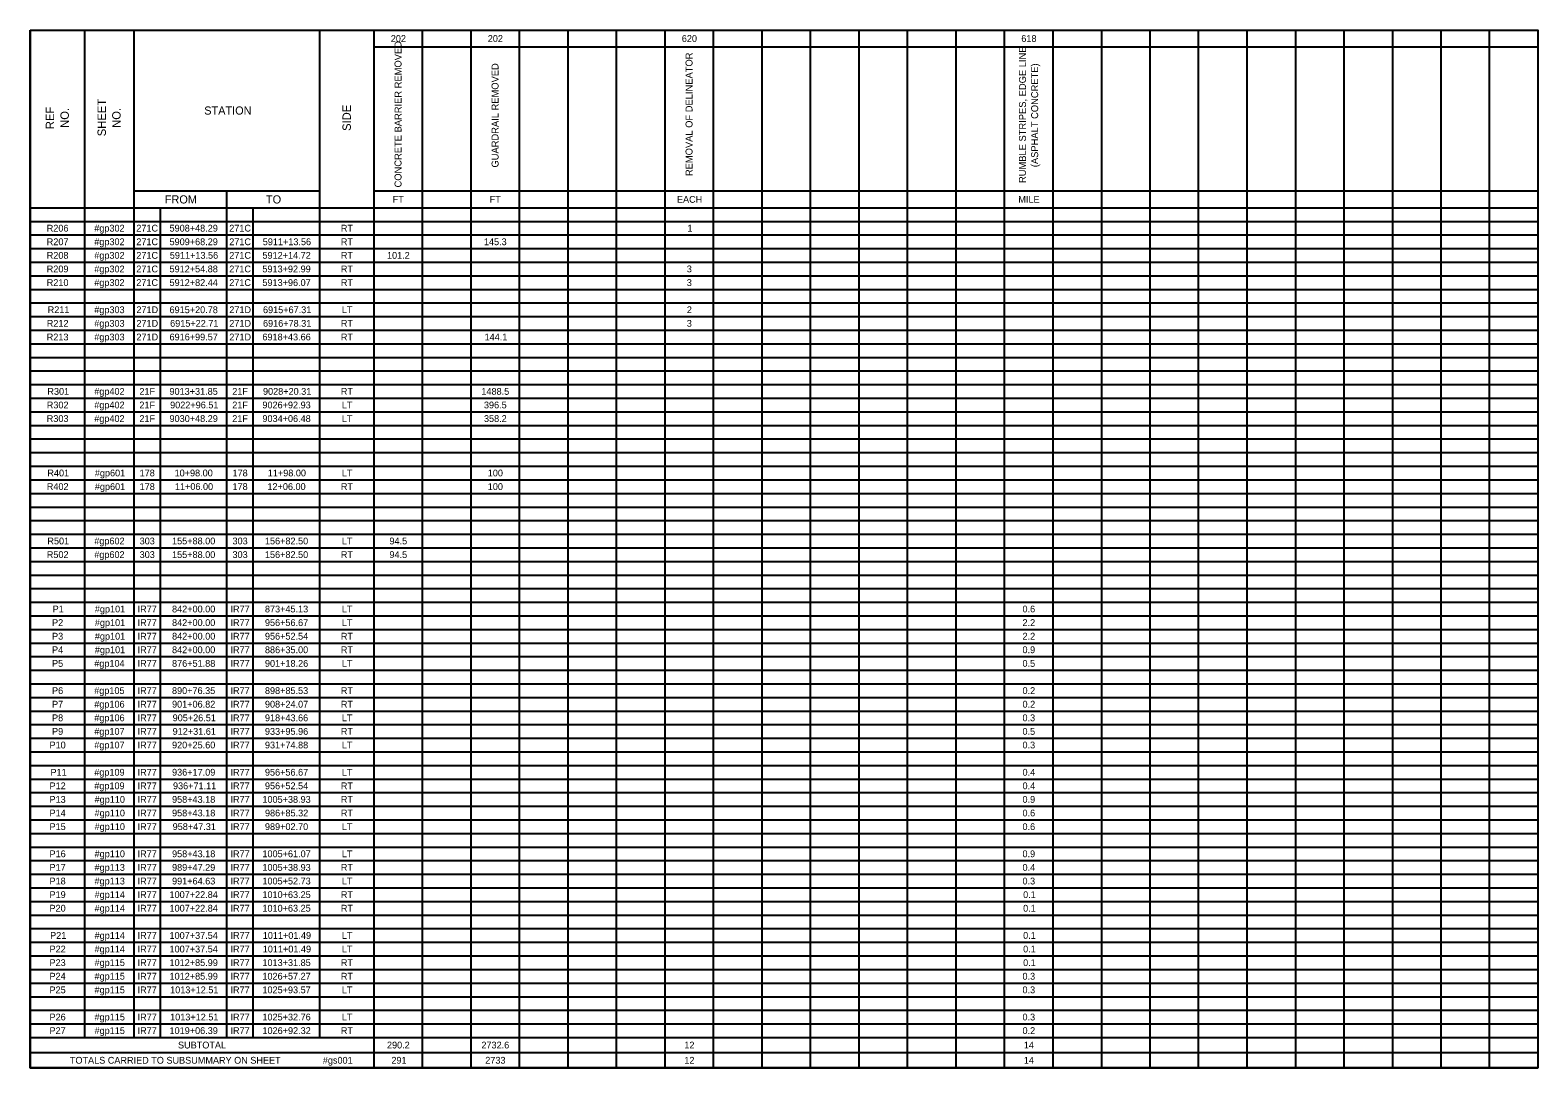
# Model space of a CAD drawing. Extents: x -542 to 295, y -281 to 32.
# Drawn here: x -16.36 to 14.14, y -70.59 to -49.59 of the extents above; entities that cross this region are included whole.
import ezdxf

# ---------------------------------------------------------------- set-up
doc = ezdxf.new("R2010")
doc.units = 0
doc.layers.add('SC_Scratch1', color=7, linetype='Continuous')
doc.layers.add('SH_Text', color=7, linetype='Continuous')

msp = doc.modelspace()

# ---------------------------------------------------------------- linework, layer by layer
at = {"layer": 'SC_Scratch1'}
msp.add_lwpolyline([(-16.359, -49.593), (14.141, -49.593), (14.141, -70.593), (-16.359, -70.593)], close=True, dxfattribs=at)
at = {"layer": 'SH_Text'}
for p, q in [((-16.359, -49.593), (14.141, -49.593)), ((-16.359, -49.593), (-16.359, -70.593)), ((-15.261, -49.593), (-15.261, -69.977)), ((-14.263, -49.593), (-14.263, -69.977)), ((-10.505, -49.593), (-10.505, -69.977)), ((-9.407, -49.593), (-9.407, -70.593)), ((-8.426, -49.593), (-8.426, -70.593)), ((-7.445, -49.593), (-7.445, -70.593)), ((-6.463, -49.593), (-6.463, -70.593)), ((-5.482, -49.593), (-5.482, -70.593)), ((-4.501, -49.593), (-4.501, -70.593)), ((-3.52, -49.593), (-3.52, -70.593)), ((-2.539, -49.593), (-2.539, -70.593)), ((-1.558, -49.593), (-1.558, -70.593)), ((-0.576, -49.593), (-0.576, -70.593)), ((0.405, -49.593), (0.405, -70.593)), ((1.386, -49.593), (1.386, -70.593)), ((2.367, -49.593), (2.367, -70.593)), ((3.348, -49.593), (3.348, -70.593)), ((4.33, -49.593), (4.33, -70.593)), ((5.311, -49.593), (5.311, -70.593)), ((6.292, -49.593), (6.292, -70.593)), ((7.273, -49.593), (7.273, -70.593)), ((8.254, -49.593), (8.254, -70.593)), ((9.236, -49.593), (9.236, -70.593)), ((10.217, -49.593), (10.217, -70.593)), ((11.198, -49.593), (11.198, -70.593)), ((12.179, -49.593), (12.179, -70.593)), ((13.16, -49.593), (13.16, -70.593)), ((14.141, -49.593), (14.141, -70.593)), ((-9.407, -49.933), (14.141, -49.933)), ((-14.263, -52.847), (-10.505, -52.847)), ((-12.384, -52.847), (-12.384, -69.977)), ((-9.407, -52.847), (14.141, -52.847)), ((-16.359, -53.187), (14.141, -53.187)), ((-13.731, -53.187), (-13.731, -69.977)), ((-11.852, -53.187), (-11.852, -69.977)), ((-16.359, -53.462), (14.141, -53.462)), ((-16.359, -53.737), (14.141, -53.737)), ((-16.359, -54.013), (14.141, -54.013)), ((-16.359, -54.288), (14.141, -54.288)), ((-16.359, -54.563), (14.141, -54.563)), ((-16.359, -54.838), (14.141, -54.838)), ((-16.359, -55.114), (14.141, -55.114)), ((-16.359, -55.389), (14.141, -55.389)), ((-16.359, -55.664), (14.141, -55.664)), ((-16.359, -55.94), (14.141, -55.94)), ((-16.359, -56.215), (14.141, -56.215)), ((-16.359, -56.49), (14.141, -56.49)), ((-16.359, -56.765), (14.141, -56.765)), ((-16.359, -57.041), (14.141, -57.041)), ((-16.359, -57.316), (14.141, -57.316)), ((-16.359, -57.591), (14.141, -57.591)), ((-16.359, -57.866), (14.141, -57.866)), ((-16.359, -58.142), (14.141, -58.142)), ((-16.359, -58.417), (14.141, -58.417)), ((-16.359, -58.692), (14.141, -58.692)), ((-16.359, -58.967), (14.141, -58.967)), ((-16.359, -59.243), (14.141, -59.243)), ((-16.359, -59.518), (14.141, -59.518)), ((-16.359, -59.793), (14.141, -59.793)), ((-16.359, -60.068), (14.141, -60.068)), ((-16.359, -60.344), (14.141, -60.344)), ((-16.359, -60.619), (14.141, -60.619)), ((-16.359, -60.894), (14.141, -60.894)), ((-16.359, -61.169), (14.141, -61.169)), ((-16.359, -61.445), (14.141, -61.445)), ((-16.359, -61.72), (14.141, -61.72)), ((-16.359, -61.995), (14.141, -61.995)), ((-16.359, -62.27), (14.141, -62.27)), ((-16.359, -62.546), (14.141, -62.546)), ((-16.359, -62.821), (14.141, -62.821)), ((-16.359, -63.096), (14.141, -63.096)), ((-16.359, -63.371), (14.141, -63.371)), ((-16.359, -63.647), (14.141, -63.647)), ((-16.359, -63.922), (14.141, -63.922)), ((-16.359, -64.197), (14.141, -64.197)), ((-16.359, -64.472), (14.141, -64.472)), ((-16.359, -64.748), (14.141, -64.748)), ((-16.359, -65.023), (14.141, -65.023)), ((-16.359, -65.298), (14.141, -65.298)), ((-16.359, -65.573), (14.141, -65.573)), ((-16.359, -65.849), (14.141, -65.849)), ((-16.359, -66.124), (14.141, -66.124)), ((-16.359, -66.399), (14.141, -66.399)), ((-16.359, -66.674), (14.141, -66.674)), ((-16.359, -66.95), (14.141, -66.95)), ((-16.359, -67.225), (14.141, -67.225)), ((-16.359, -67.5), (14.141, -67.5)), ((-16.359, -67.775), (14.141, -67.775)), ((-16.359, -68.051), (14.141, -68.051)), ((-16.359, -68.326), (14.141, -68.326)), ((-16.359, -68.601), (14.141, -68.601)), ((-16.359, -68.876), (14.141, -68.876)), ((-16.359, -69.152), (14.141, -69.152)), ((-16.359, -69.427), (14.141, -69.427)), ((-16.359, -69.702), (14.141, -69.702)), ((-16.359, -69.977), (14.141, -69.977)), ((-16.359, -70.285), (14.141, -70.285)), ((-16.359, -70.593), (14.141, -70.593))]:
    msp.add_line(p, q, dxfattribs=at)

# ---------------------------------------------------------------- texts
for s, height, p in [('202', 0.1376, (-9.063, -49.831)), ('202', 0.1376, (-7.101, -49.831)), ('620', 0.1376, (-3.176, -49.831)), ('618', 0.1376, (3.692, -49.831)), ('STATION', 0.1652, (-12.837, -51.302)), ('FROM', 0.1652, (-13.635, -53.1)), ('TO', 0.1652, (-11.588, -53.1)), ('FT', 0.1376, (-9.025, -53.086)), ('FT', 0.1376, (-7.062, -53.086)), ('EACH', 0.1376, (-3.274, -53.086)), ('MILE', 0.1376, (3.632, -53.086)), ('R206', 0.1376, (-16.023, -53.669)), ('#gp302', 0.1376, (-15.062, -53.669)), ('271C', 0.1376, (-14.211, -53.669)), ('5908+48.29', 0.1376, (-13.539, -53.669)), ('271C', 0.1376, (-12.331, -53.669)), ('RT', 0.1376, (-10.073, -53.669)), ('1', 0.138, (-3.062, -53.669)), ('R207', 0.1376, (-16.023, -53.944)), ('#gp302', 0.1376, (-15.062, -53.944)), ('271C', 0.1376, (-14.211, -53.944)), ('5909+68.29', 0.1376, (-13.539, -53.944)), ('271C', 0.1376, (-12.331, -53.944)), ('5911+13.56', 0.1376, (-11.653, -53.944)), ('RT', 0.1376, (-10.073, -53.944)), ('145.3', 0.1376, (-7.179, -53.944)), ('R208', 0.1376, (-16.023, -54.219)), ('#gp302', 0.1376, (-15.062, -54.219)), ('271C', 0.1376, (-14.211, -54.219)), ('5911+13.56', 0.1376, (-13.533, -54.219)), ('271C', 0.1376, (-12.331, -54.219)), ('5912+14.72', 0.1376, (-11.659, -54.219)), ('RT', 0.1376, (-10.073, -54.219)), ('101.2', 0.1376, (-9.14, -54.219)), ('R209', 0.1376, (-16.023, -54.494)), ('#gp302', 0.1376, (-15.062, -54.494)), ('271C', 0.1376, (-14.211, -54.494)), ('5912+54.88', 0.1376, (-13.539, -54.494)), ('271C', 0.1376, (-12.331, -54.494)), ('5913+92.99', 0.1376, (-11.66, -54.494)), ('RT', 0.1376, (-10.073, -54.494)), ('3', 0.138, (-3.075, -54.494)), ('R210', 0.1376, (-16.023, -54.77)), ('#gp302', 0.1376, (-15.062, -54.77)), ('271C', 0.1376, (-14.211, -54.77)), ('5912+82.44', 0.1376, (-13.539, -54.77)), ('271C', 0.1376, (-12.331, -54.77)), ('5913+96.07', 0.1376, (-11.66, -54.77)), ('RT', 0.1376, (-10.073, -54.77)), ('3', 0.138, (-3.075, -54.77)), ('R211', 0.1376, (-16.004, -55.32)), ('#gp303', 0.1376, (-15.062, -55.32)), ('271D', 0.1376, (-14.209, -55.32)), ('6915+20.78', 0.1376, (-13.539, -55.32)), ('271D', 0.1376, (-12.33, -55.32)), ('6915+67.31', 0.1376, (-11.648, -55.32)), ('LT', 0.1376, (-10.053, -55.32)), ('2', 0.138, (-3.074, -55.32)), ('R212', 0.1376, (-16.022, -55.595)), ('#gp303', 0.1376, (-15.062, -55.595)), ('271D', 0.1376, (-14.209, -55.595)), ('6915+22.71', 0.1376, (-13.527, -55.595)), ('271D', 0.1376, (-12.33, -55.595)), ('6916+78.31', 0.1376, (-11.648, -55.595)), ('RT', 0.1376, (-10.073, -55.595)), ('3', 0.138, (-3.075, -55.595)), ('R213', 0.1376, (-16.023, -55.871)), ('#gp303', 0.1376, (-15.062, -55.871)), ('271D', 0.1376, (-14.209, -55.871)), ('6916+99.57', 0.1376, (-13.539, -55.871)), ('271D', 0.1376, (-12.33, -55.871)), ('6918+43.66', 0.1376, (-11.66, -55.871)), ('RT', 0.1376, (-10.073, -55.871)), ('144.1', 0.1376, (-7.166, -55.871)), ('R301', 0.1376, (-16.01, -56.972)), ('#gp402', 0.1376, (-15.062, -56.972)), ('21F', 0.1376, (-14.149, -56.972)), ('9013+31.85', 0.1376, (-13.54, -56.972)), ('21F', 0.1376, (-12.27, -56.972)), ('9028+20.31', 0.1376, (-11.648, -56.972)), ('RT', 0.1376, (-10.073, -56.972)), ('1488.5', 0.1376, (-7.23, -56.972)), ('R302', 0.1376, (-16.022, -57.247)), ('#gp402', 0.1376, (-15.062, -57.247)), ('21F', 0.1376, (-14.149, -57.247)), ('9022+96.51', 0.1376, (-13.527, -57.247)), ('21F', 0.1376, (-12.27, -57.247)), ('9026+92.93', 0.1376, (-11.66, -57.247)), ('LT', 0.1376, (-10.053, -57.247)), ('396.5', 0.1376, (-7.179, -57.247)), ('R303', 0.1376, (-16.023, -57.522)), ('#gp402', 0.1376, (-15.062, -57.522)), ('21F', 0.1376, (-14.149, -57.522)), ('9030+48.29', 0.1376, (-13.539, -57.522)), ('21F', 0.1376, (-12.27, -57.522)), ('9034+06.48', 0.1376, (-11.66, -57.522)), ('LT', 0.1376, (-10.053, -57.522)), ('358.2', 0.1376, (-7.178, -57.522)), ('R401', 0.1376, (-16.01, -58.623)), ('#gp601', 0.1376, (-15.05, -58.623)), ('178', 0.1376, (-14.144, -58.623)), ('10+98.00', 0.1376, (-13.437, -58.623)), ('178', 0.1376, (-12.265, -58.623)), ('11+98.00', 0.1376, (-11.551, -58.623)), ('LT', 0.1376, (-10.053, -58.623)), ('100', 0.1376, (-7.101, -58.623)), ('R402', 0.1376, (-16.022, -58.898)), ('#gp601', 0.1376, (-15.05, -58.898)), ('178', 0.1376, (-14.144, -58.898)), ('11+06.00', 0.1376, (-13.43, -58.898)), ('178', 0.1376, (-12.265, -58.898)), ('12+06.00', 0.1376, (-11.558, -58.898)), ('RT', 0.1376, (-10.073, -58.898)), ('100', 0.1376, (-7.101, -58.898)), ('R501', 0.1376, (-16.01, -59.999)), ('#gp602', 0.1376, (-15.062, -59.999)), ('303', 0.1376, (-14.144, -59.999)), ('155+88.00', 0.1376, (-13.488, -59.999)), ('303', 0.1376, (-12.265, -59.999)), ('156+82.50', 0.1376, (-11.609, -59.999)), ('LT', 0.1376, (-10.053, -59.999)), ('94.5', 0.1376, (-9.09, -59.999)), ('R502', 0.1376, (-16.022, -60.275)), ('#gp602', 0.1376, (-15.062, -60.275)), ('303', 0.1376, (-14.144, -60.275)), ('155+88.00', 0.1376, (-13.488, -60.275)), ('303', 0.1376, (-12.265, -60.275)), ('156+82.50', 0.1376, (-11.609, -60.275)), ('RT', 0.1376, (-10.073, -60.275)), ('94.5', 0.1376, (-9.09, -60.275)), ('P1', 0.1376, (-15.904, -61.376)), ('#gp101', 0.1376, (-15.05, -61.376)), ('IR77', 0.1376, (-14.185, -61.376)), ('842+00.00', 0.1376, (-13.488, -61.376)), ('IR77', 0.1376, (-12.306, -61.376)), ('873+45.13', 0.1376, (-11.609, -61.376)), ('LT', 0.1376, (-10.053, -61.376)), ('0.6', 0.1376, (3.716, -61.376)), ('P2', 0.1376, (-15.915, -61.651)), ('#gp101', 0.1376, (-15.05, -61.651)), ('IR77', 0.1376, (-14.185, -61.651)), ('842+00.00', 0.1376, (-13.488, -61.651)), ('IR77', 0.1376, (-12.306, -61.651)), ('956+56.67', 0.1376, (-11.609, -61.651)), ('LT', 0.1376, (-10.053, -61.651)), ('2.2', 0.1376, (3.717, -61.651)), ('P3', 0.1376, (-15.916, -61.926)), ('#gp101', 0.1376, (-15.05, -61.926)), ('IR77', 0.1376, (-14.185, -61.926)), ('842+00.00', 0.1376, (-13.488, -61.926)), ('IR77', 0.1376, (-12.306, -61.926)), ('956+52.54', 0.1376, (-11.609, -61.926)), ('RT', 0.1376, (-10.073, -61.926)), ('2.2', 0.1376, (3.717, -61.926)), ('P4', 0.1376, (-15.916, -62.201)), ('#gp101', 0.1376, (-15.05, -62.201)), ('IR77', 0.1376, (-14.185, -62.201)), ('842+00.00', 0.1376, (-13.488, -62.201)), ('IR77', 0.1376, (-12.306, -62.201)), ('886+35.00', 0.1376, (-11.609, -62.201)), ('RT', 0.1376, (-10.073, -62.201)), ('0.9', 0.1376, (3.716, -62.201)), ('P5', 0.1376, (-15.916, -62.477)), ('#gp104', 0.1376, (-15.062, -62.477)), ('IR77', 0.1376, (-14.185, -62.477)), ('876+51.88', 0.1376, (-13.488, -62.477)), ('IR77', 0.1376, (-12.306, -62.477)), ('901+18.26', 0.1376, (-11.609, -62.477)), ('LT', 0.1376, (-10.053, -62.477)), ('0.5', 0.1376, (3.716, -62.477)), ('P6', 0.1376, (-15.916, -63.027)), ('#gp105', 0.1376, (-15.063, -63.027)), ('IR77', 0.1376, (-14.185, -63.027)), ('890+76.35', 0.1376, (-13.489, -63.027)), ('IR77', 0.1376, (-12.306, -63.027)), ('898+85.53', 0.1376, (-11.609, -63.027)), ('RT', 0.1376, (-10.073, -63.027)), ('0.2', 0.1376, (3.717, -63.027)), ('P7', 0.1376, (-15.916, -63.302)), ('P8', 0.1376, (-15.916, -63.578)), ('#gp106', 0.1376, (-15.062, -63.302)), ('#gp106', 0.1376, (-15.062, -63.578)), ('IR77', 0.1376, (-14.185, -63.302)), ('901+06.82', 0.1376, (-13.488, -63.302)), ('905+26.51', 0.1376, (-13.476, -63.578)), ('IR77', 0.1376, (-12.306, -63.302)), ('908+24.07', 0.1376, (-11.609, -63.302)), ('918+43.66', 0.1376, (-11.609, -63.578)), ('RT', 0.1376, (-10.073, -63.302)), ('0.2', 0.1376, (3.717, -63.302)), ('0.3', 0.1376, (3.716, -63.578)), ('P9', 0.1376, (-15.916, -63.853)), ('#gp107', 0.1376, (-15.062, -63.853)), ('IR77', 0.1376, (-14.185, -63.578)), ('IR77', 0.1376, (-14.185, -63.853)), ('912+31.61', 0.1376, (-13.476, -63.853)), ('IR77', 0.1376, (-12.306, -63.578)), ('IR77', 0.1376, (-12.306, -63.853)), ('933+95.96', 0.1376, (-11.609, -63.853)), ('RT', 0.1376, (-10.073, -63.853)), ('LT', 0.1376, (-10.053, -63.578)), ('0.5', 0.1376, (3.716, -63.853)), ('P10', 0.1376, (-15.967, -64.128)), ('#gp107', 0.1376, (-15.062, -64.128)), ('IR77', 0.1376, (-14.185, -64.128)), ('920+25.60', 0.1376, (-13.488, -64.128)), ('IR77', 0.1376, (-12.306, -64.128)), ('931+74.88', 0.1376, (-11.609, -64.128)), ('LT', 0.1376, (-10.053, -64.128)), ('0.3', 0.1376, (3.716, -64.128)), ('P11', 0.1376, (-15.948, -64.679)), ('#gp109', 0.1376, (-15.062, -64.679)), ('IR77', 0.1376, (-14.185, -64.679)), ('936+17.09', 0.1376, (-13.488, -64.679)), ('IR77', 0.1376, (-12.306, -64.679)), ('956+56.67', 0.1376, (-11.609, -64.679)), ('LT', 0.1376, (-10.053, -64.679)), ('0.4', 0.1376, (3.717, -64.679)), ('P12', 0.1376, (-15.966, -64.954)), ('#gp109', 0.1376, (-15.062, -64.954)), ('IR77', 0.1376, (-14.185, -64.954)), ('936+71.11', 0.1376, (-13.469, -64.954)), ('IR77', 0.1376, (-12.306, -64.954)), ('956+52.54', 0.1376, (-11.609, -64.954)), ('RT', 0.1376, (-10.073, -64.954)), ('0.4', 0.1376, (3.717, -64.954)), ('P13', 0.1376, (-15.967, -65.229)), ('#gp110', 0.1376, (-15.055, -65.229)), ('IR77', 0.1376, (-14.185, -65.229)), ('958+43.18', 0.1376, (-13.488, -65.229)), ('IR77', 0.1376, (-12.306, -65.229)), ('1005+38.93', 0.1376, (-11.66, -65.229)), ('RT', 0.1376, (-10.073, -65.229)), ('0.9', 0.1376, (3.716, -65.229)), ('P14', 0.1376, (-15.967, -65.504)), ('#gp110', 0.1376, (-15.055, -65.504)), ('IR77', 0.1376, (-14.185, -65.504)), ('958+43.18', 0.1376, (-13.488, -65.504)), ('IR77', 0.1376, (-12.306, -65.504)), ('986+85.32', 0.1376, (-11.608, -65.504)), ('RT', 0.1376, (-10.073, -65.504)), ('0.6', 0.1376, (3.716, -65.504)), ('P15', 0.1376, (-15.967, -65.78)), ('#gp110', 0.1376, (-15.055, -65.78)), ('IR77', 0.1376, (-14.185, -65.78)), ('958+47.31', 0.1376, (-13.476, -65.78)), ('IR77', 0.1376, (-12.306, -65.78)), ('989+02.70', 0.1376, (-11.609, -65.78)), ('LT', 0.1376, (-10.053, -65.78)), ('0.6', 0.1376, (3.716, -65.78)), ('P16', 0.1376, (-15.967, -66.33)), ('P17', 0.1376, (-15.967, -66.605)), ('#gp110', 0.1376, (-15.055, -66.33)), ('#gp113', 0.1376, (-15.056, -66.605)), ('IR77', 0.1376, (-14.185, -66.33)), ('IR77', 0.1376, (-14.185, -66.605)), ('958+43.18', 0.1376, (-13.488, -66.33)), ('989+47.29', 0.1376, (-13.488, -66.605)), ('IR77', 0.1376, (-12.306, -66.33)), ('IR77', 0.1376, (-12.306, -66.605)), ('1005+61.07', 0.1376, (-11.66, -66.33)), ('1005+38.93', 0.1376, (-11.66, -66.605)), ('RT', 0.1376, (-10.073, -66.605)), ('LT', 0.1376, (-10.053, -66.33)), ('0.9', 0.1376, (3.716, -66.33)), ('0.4', 0.1376, (3.717, -66.605)), ('P18', 0.1376, (-15.967, -66.881)), ('#gp113', 0.1376, (-15.056, -66.881)), ('IR77', 0.1376, (-14.185, -66.881)), ('991+64.63', 0.1376, (-13.488, -66.881)), ('IR77', 0.1376, (-12.306, -66.881)), ('1005+52.73', 0.1376, (-11.66, -66.881)), ('LT', 0.1376, (-10.053, -66.881)), ('0.3', 0.1376, (3.716, -66.881)), ('P19', 0.1376, (-15.967, -67.156)), ('#gp114', 0.1376, (-15.055, -67.156)), ('IR77', 0.1376, (-14.185, -67.156)), ('1007+22.84', 0.1376, (-13.539, -67.156)), ('IR77', 0.1376, (-12.306, -67.156)), ('1010+63.25', 0.1376, (-11.66, -67.156)), ('RT', 0.1376, (-10.073, -67.156)), ('0.1', 0.1376, (3.729, -67.156)), ('P20', 0.1376, (-15.967, -67.431)), ('#gp114', 0.1376, (-15.055, -67.431)), ('IR77', 0.1376, (-14.185, -67.431)), ('1007+22.84', 0.1376, (-13.539, -67.431)), ('IR77', 0.1376, (-12.306, -67.431)), ('1010+63.25', 0.1376, (-11.66, -67.431)), ('RT', 0.1376, (-10.073, -67.431)), ('0.1', 0.1376, (3.729, -67.431)), ('P21', 0.1376, (-15.955, -67.982)), ('#gp114', 0.1376, (-15.055, -67.982)), ('IR77', 0.1376, (-14.185, -67.982)), ('1007+37.54', 0.1376, (-13.539, -67.982)), ('IR77', 0.1376, (-12.306, -67.982)), ('1011+01.49', 0.1376, (-11.653, -67.982)), ('LT', 0.1376, (-10.053, -67.982)), ('0.1', 0.1376, (3.729, -67.982)), ('P22', 0.1376, (-15.966, -68.257)), ('#gp114', 0.1376, (-15.055, -68.257)), ('IR77', 0.1376, (-14.185, -68.257)), ('1007+37.54', 0.1376, (-13.539, -68.257)), ('IR77', 0.1376, (-12.306, -68.257)), ('1011+01.49', 0.1376, (-11.653, -68.257)), ('LT', 0.1376, (-10.053, -68.257)), ('0.1', 0.1376, (3.729, -68.257)), ('P23', 0.1376, (-15.967, -68.532)), ('#gp115', 0.1376, (-15.056, -68.532)), ('IR77', 0.1376, (-14.185, -68.532)), ('1012+85.99', 0.1376, (-13.539, -68.532)), ('IR77', 0.1376, (-12.306, -68.532)), ('1013+31.85', 0.1376, (-11.66, -68.532)), ('RT', 0.1376, (-10.073, -68.532)), ('0.1', 0.1376, (3.729, -68.532)), ('P24', 0.1376, (-15.967, -68.807)), ('#gp115', 0.1376, (-15.056, -68.807)), ('IR77', 0.1376, (-14.185, -68.807)), ('1012+85.99', 0.1376, (-13.539, -68.807)), ('IR77', 0.1376, (-12.306, -68.807)), ('1026+57.27', 0.1376, (-11.66, -68.807)), ('RT', 0.1376, (-10.073, -68.807)), ('0.3', 0.1376, (3.716, -68.807)), ('P25', 0.1376, (-15.967, -69.083)), ('#gp115', 0.1376, (-15.056, -69.083)), ('IR77', 0.1376, (-14.185, -69.083)), ('1013+12.51', 0.1376, (-13.527, -69.083)), ('IR77', 0.1376, (-12.306, -69.083)), ('1025+93.57', 0.1376, (-11.66, -69.083)), ('LT', 0.1376, (-10.053, -69.083)), ('0.3', 0.1376, (3.716, -69.083)), ('P26', 0.1376, (-15.967, -69.633)), ('#gp115', 0.1376, (-15.056, -69.633)), ('IR77', 0.1376, (-14.185, -69.633)), ('1013+12.51', 0.1376, (-13.527, -69.633)), ('IR77', 0.1376, (-12.306, -69.633)), ('1025+32.76', 0.1376, (-11.66, -69.633)), ('LT', 0.1376, (-10.053, -69.633)), ('0.3', 0.1376, (3.716, -69.633)), ('P27', 0.1376, (-15.967, -69.908)), ('#gp115', 0.1376, (-15.056, -69.908)), ('IR77', 0.1376, (-14.185, -69.908)), ('1019+06.39', 0.1376, (-13.539, -69.908)), ('IR77', 0.1376, (-12.306, -69.908)), ('1026+92.32', 0.1376, (-11.659, -69.908)), ('RT', 0.1376, (-10.073, -69.908)), ('0.2', 0.1376, (3.717, -69.908)), ('SUBTOTAL', 0.1376, (-13.367, -70.2)), ('290.2', 0.1376, (-9.14, -70.2)), ('2732.6', 0.1376, (-7.23, -70.2)), ('12', 0.1376, (-3.125, -70.2)), ('14', 0.1376, (3.743, -70.2)), ('TOTALS CARRIED TO SUBSUMMARY ON SHEET', 0.13763, (-15.555, -70.508)), ('#gs001', 0.1376, (-10.438, -70.508)), ('291', 0.1376, (-9.051, -70.508)), ('2733', 0.1376, (-7.152, -70.508)), ('12', 0.1376, (-3.125, -70.508)), ('14', 0.1376, (3.743, -70.508))]:
    msp.add_text(s, height=height, dxfattribs=at).set_placement(p)
for s, height, p in [('CONCRETE BARRIER REMOVED', 0.14136, (-8.846, -52.776)), ('RUMBLE STRIPES, EDGE LINE ', 0.14136, (3.786, -52.686)), ('GUARDRAIL REMOVED', 0.14136, (-6.883, -52.373)), ('REMOVAL OF DELINEATOR', 0.14136, (-2.959, -52.546)), ('(ASPHALT CONCRETE)', 0.14136, (4.033, -52.366)), ('REF', 0.1696, (-15.873, -51.596)), ('NO.', 0.1696, (-15.576, -51.57)), ('SHEET', 0.1696, (-14.826, -51.74)), ('NO.', 0.1696, (-14.529, -51.57)), ('SIDE', 0.1696, (-9.871, -51.632))]:
    msp.add_text(s, height=height, rotation=90, dxfattribs=at).set_placement(p)

doc.saveas('drawing.dxf')
